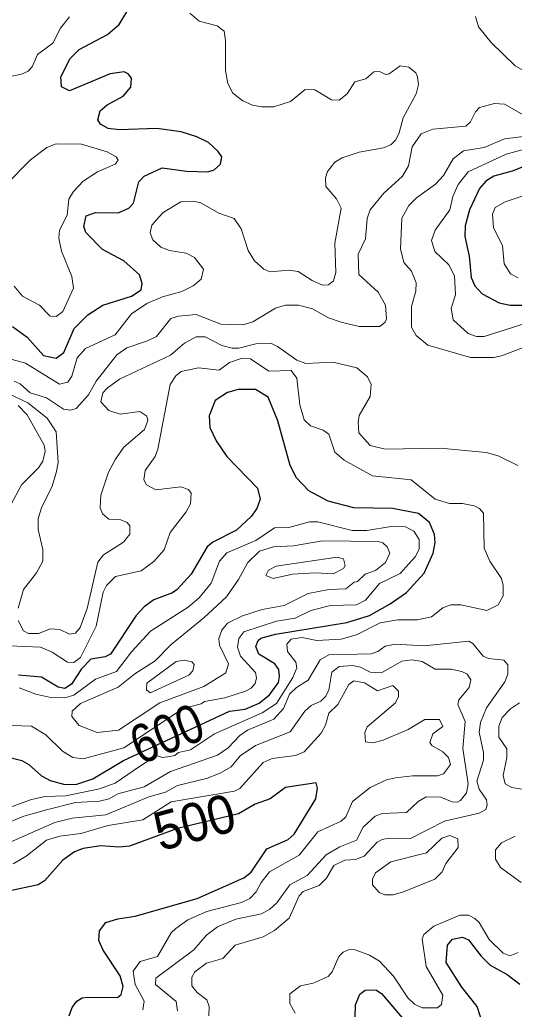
# Model space of a CAD drawing. Extents: x 577 to 602.9, y 7483.8 to 7511.6.
# Drawn here: x 588.93 to 589.958, y 7495.736 to 7497.794 of the extents above; entities that cross this region are included whole.
import ezdxf
from ezdxf.enums import TextEntityAlignment as Align

# ---------------------------------------------------------------- set-up
doc = ezdxf.new("R2010")
doc.units = 0
doc.header["$LTSCALE"] = 0.032
doc.layers.add('1', color=7, linetype='Continuous', lineweight=25)
doc.layers.add('2', color=7, linetype='Continuous', lineweight=13)
doc.layers.add('61', color=7, linetype='Continuous')

msp = doc.modelspace()

# ---------------------------------------------------------------- linework, layer by layer
at = {"layer": '1'}
for points in [[(589.277, 7497.4791), (589.3215, 7497.4775), (589.3342, 7497.4822), (589.3477, 7497.4934), (589.3501, 7497.5093), (589.343, 7497.5204), (589.3223, 7497.5387), (589.2984, 7497.5506), (589.2658, 7497.561), (589.215, 7497.5681), (589.137, 7497.5649), (589.114, 7497.5681), (589.0981, 7497.5769), (589.0925, 7497.5856), (589.0973, 7497.6047), (589.1116, 7497.6174), (589.145, 7497.6349), (589.1609, 7497.654), (589.1625, 7497.6723), (589.1553, 7497.6818), (589.1474, 7497.6858), (589.1179, 7497.6818), (589.0337, 7497.6461), (589.017, 7497.6548), (589.0154, 7497.6755), (589.0352, 7497.7136), (589.0535, 7497.7319), (589.1124, 7497.7637), (589.137, 7497.7844), (589.1688, 7497.8377)], [(590.061, 7497.5212), (589.9537, 7497.4791), (589.9155, 7497.4687), (589.8988, 7497.4584), (589.8861, 7497.4433), (589.8654, 7497.3988), (589.8559, 7497.3654), (589.8551, 7497.3431), (589.8646, 7497.3025), (589.8686, 7497.258), (589.8765, 7497.2405), (589.8916, 7497.2238), (589.9266, 7497.2055), (589.9497, 7497.2008), (589.991, 7497.2008)], [(588.9152, 7497.1562), (588.9454, 7497.134), (588.9796, 7497.0958), (589.0058, 7497.0902), (589.0217, 7497.1022), (589.0432, 7497.1522), (589.0718, 7497.1801), (589.1028, 7497.2008), (589.1625, 7497.219), (589.1824, 7497.2326), (589.1847, 7497.2453), (589.1792, 7497.2636), (589.1466, 7497.293), (589.102, 7497.3161), (589.0678, 7497.3518), (589.0631, 7497.3638), (589.0686, 7497.386), (589.0877, 7497.3932), (589.1346, 7497.3924), (589.1569, 7497.4019), (589.1664, 7497.4123), (589.1776, 7497.4568), (589.1887, 7497.4687), (589.2261, 7497.4862), (589.277, 7497.4791)], [(588.8937, 7496.264), (588.9343, 7496.2537), (588.9494, 7496.245), (588.9756, 7496.2219), (588.9931, 7496.2124), (589.0241, 7496.2036), (589.0488, 7496.2044), (589.0821, 7496.2153), (589.1456, 7496.2538), (589.366, 7496.3563), (589.3986, 7496.3603), (589.4281, 7496.373), (589.4495, 7496.3905), (589.4678, 7496.4159), (589.4702, 7496.4286), (589.4686, 7496.443), (589.4607, 7496.4549), (589.4273, 7496.4748), (589.4209, 7496.4907), (589.4257, 7496.5034), (589.4312, 7496.5082), (589.4619, 7496.5166), (589.6102, 7496.5408), (589.6571, 7496.5551), (589.7, 7496.5797), (589.7342, 7496.6028), (589.7708, 7496.6433), (589.7899, 7496.6847), (589.7938, 7496.7069), (589.7923, 7496.7236), (589.7819, 7496.7483), (589.7589, 7496.7674), (589.7048, 7496.7777), (589.6245, 7496.7793), (589.5712, 7496.7928), (589.5314, 7496.8143), (589.5052, 7496.8413), (589.4925, 7496.8668), (589.467, 7496.9598), (589.4464, 7497.0091), (589.4201, 7497.025), (589.3843, 7497.025), (589.3621, 7497.0187), (589.3366, 7497.002), (589.3239, 7496.9702), (589.3255, 7496.9463), (589.3382, 7496.9185), (589.3605, 7496.8859), (589.4241, 7496.8199), (589.4297, 7496.7968), (589.4233, 7496.7777), (589.4114, 7496.761), (589.3811, 7496.7324), (589.3318, 7496.7077), (589.3199, 7496.6982), (589.2865, 7496.6409), (589.2571, 7496.6091), (589.2476, 7496.602), (589.2086, 7496.5877), (589.1887, 7496.5734), (589.172, 7496.5551), (589.1187, 7496.4748), (589.1076, 7496.4692), (589.0782, 7496.4644), (589.0583, 7496.4445), (589.0376, 7496.4127), (589.0241, 7496.4032), (589.0098, 7496.4064), (588.9756, 7496.427), (588.9279, 7496.431)], [(589.0329, 7495.7225), (589.0392, 7495.74), (589.0488, 7495.7535), (589.0599, 7495.7599), (589.0718, 7495.7615), (589.1331, 7495.7607), (589.141, 7495.7671), (589.145, 7495.7838), (589.1386, 7495.806), (589.1036, 7495.8593), (589.0949, 7495.8792), (589.0957, 7495.8991), (589.1092, 7495.9165), (589.1338, 7495.9245), (589.1704, 7495.9301), (589.2992, 7495.9666), (589.3963, 7496.0096), (589.4114, 7496.0215), (589.444, 7496.07), (589.4885, 7496.0891), (589.5004, 7496.1002), (589.5457, 7496.1742), (589.5489, 7496.1964), (589.5464, 7496.2074), (589.4829, 7496.1972), (589.4511, 7496.1742), (589.4193, 7496.163), (589.3851, 7496.1424), (589.2582, 7496.112), (589.1585, 7496.0756), (589.1362, 7496.0732), (589.0989, 7496.0764), (589.0623, 7496.0708), (589.044, 7496.0637), (589.0201, 7496.0462), (588.982, 7496.0032), (588.9685, 7495.9953), (588.8547, 7495.9706)], [(589.8956, 7495.6971), (589.8813, 7495.7424), (589.8495, 7495.7822), (589.8169, 7495.8338), (589.8193, 7495.8696), (589.8296, 7495.8824), (589.8503, 7495.8863), (589.863, 7495.8808), (589.8893, 7495.8466), (589.9083, 7495.8283), (589.9433, 7495.8084), (589.9696, 7495.7885)], [(589.6277, 7495.7201), (589.6284, 7495.7456), (589.6372, 7495.7678), (589.6483, 7495.7758), (589.6706, 7495.7766), (589.6825, 7495.7694), (589.7334, 7495.709)]]:
    msp.add_lwpolyline(points, dxfattribs=at)
at = {"layer": '2'}
for points in [[(588.9335, 7497.681), (588.9478, 7497.6874), (588.9557, 7497.6961), (588.9669, 7497.7216), (588.9987, 7497.7454), (589.0146, 7497.7765), (589.0337, 7497.8003)], [(589.2841, 7497.8075), (589.3032, 7497.7908), (589.3406, 7497.7812), (589.3549, 7497.7701), (589.3581, 7497.751), (589.3581, 7497.6882), (589.3629, 7497.6612), (589.3732, 7497.6413), (589.3939, 7497.6254), (589.4137, 7497.6166), (589.4328, 7497.6127), (589.4583, 7497.6127), (589.4933, 7497.6238), (589.5235, 7497.6492), (589.5434, 7497.6484), (589.5783, 7497.6278), (589.5943, 7497.627), (589.611, 7497.6397), (589.6269, 7497.6651), (589.6499, 7497.6715), (589.6666, 7497.6858), (589.6777, 7497.6866), (589.6913, 7497.6802), (589.6984, 7497.6818), (589.7207, 7497.6985), (589.739, 7497.6954), (589.7533, 7497.6834), (589.7573, 7497.6755), (589.7589, 7497.6596), (589.7541, 7497.6397), (589.727, 7497.5904), (589.7191, 7497.5586), (589.7119, 7497.5443), (589.7024, 7497.5347), (589.6865, 7497.5276), (589.6356, 7497.5188), (589.6006, 7497.5069), (589.5855, 7497.4981), (589.5696, 7497.4783), (589.5656, 7497.4655), (589.5664, 7497.4473), (589.5887, 7497.4218), (589.5982, 7497.4019), (589.5855, 7497.3296), (589.5871, 7497.2683), (589.5823, 7497.2508), (589.572, 7497.2429), (589.5593, 7497.2421), (589.5378, 7497.2516)], [(590.5493, 7497.8114), (590.4809, 7497.7908), (590.4276, 7497.7494), (590.368, 7497.7319), (590.3505, 7497.716), (590.3354, 7497.6906), (590.3258, 7497.6842), (590.3123, 7497.6842), (590.2908, 7497.7033), (590.2805, 7497.7049), (590.2598, 7497.6985), (590.2296, 7497.6779), (590.2034, 7497.6707), (590.158, 7497.6755), (590.1008, 7497.6612), (590.0515, 7497.6612), (589.9958, 7497.6779), (589.96, 7497.6985), (589.9099, 7497.747), (589.8837, 7497.7796), (589.8773, 7497.8011)], [(588.8738, 7497.6683), (588.9335, 7497.681)], [(589.9879, 7497.5904), (589.9378, 7497.6182), (589.9171, 7497.6198), (589.8861, 7497.6119), (589.8773, 7497.6023), (589.867, 7497.5816), (589.8575, 7497.5729), (589.7891, 7497.5665), (589.7644, 7497.557), (589.7461, 7497.53), (589.7382, 7497.4902), (589.7255, 7497.4687), (589.6873, 7497.4337), (589.6587, 7497.3988), (589.6523, 7497.3805), (589.6491, 7497.3383), (589.634, 7497.3065), (589.6348, 7497.2644), (589.6754, 7497.2278), (589.6905, 7497.2008), (589.6929, 7497.1721), (589.6897, 7497.165), (589.6785, 7497.1562), (589.6356, 7497.1562), (589.5982, 7497.165), (589.572, 7497.1745)], [(589.9751, 7497.1117), (589.9314, 7497.095), (589.9155, 7497.0918), (589.867, 7497.0918), (589.7787, 7497.1173), (589.7541, 7497.1371), (589.7445, 7497.1546), (589.7445, 7497.1976), (589.7533, 7497.2294), (589.7541, 7497.2469), (589.7445, 7497.2715), (589.7286, 7497.289), (589.7215, 7497.3176), (589.7247, 7497.3813), (589.739, 7497.4075), (589.7549, 7497.4234), (589.7946, 7497.452), (589.8113, 7497.4703), (589.8312, 7497.5045), (589.8527, 7497.5212), (589.8956, 7497.5284), (589.9378, 7497.5467), (590.0459, 7497.5594)], [(590.092, 7497.5554), (589.941, 7497.5148), (589.8622, 7497.4775), (589.8416, 7497.4512), (589.8304, 7497.4266), (589.8241, 7497.3988), (589.7938, 7497.3566), (589.7859, 7497.3351), (589.793, 7497.3121), (589.8225, 7497.2842), (589.8336, 7497.2612), (589.836, 7497.2222), (589.8272, 7497.1944), (589.8312, 7497.1697), (589.8622, 7497.1419), (589.8797, 7497.1355), (589.8956, 7497.1355), (590.0173, 7497.1745)], [(588.9184, 7497.2397), (588.9358, 7497.219), (588.9716, 7497.2008), (588.9931, 7497.1777), (589.0058, 7497.1769), (589.0201, 7497.1872), (589.0416, 7497.2357), (589.0384, 7497.2604), (589.017, 7497.3129), (589.0114, 7497.3399), (589.013, 7497.3566), (589.0289, 7497.3876), (589.0321, 7497.421), (589.0416, 7497.4369), (589.0623, 7497.4584), (589.0917, 7497.4775), (589.1283, 7497.4934), (589.1346, 7497.5021), (589.1307, 7497.5093), (589.1116, 7497.5196), (589.0583, 7497.5355), (589.0058, 7497.5363), (588.9867, 7497.5284), (588.9525, 7497.5029), (588.9001, 7497.4496)], [(589.9664, 7497.2572), (589.9505, 7497.266), (589.937, 7497.2866), (589.9338, 7497.3248), (589.9147, 7497.3614), (589.9131, 7497.39), (589.9187, 7497.4035), (589.9394, 7497.4155), (590.0308, 7497.4457)], [(589.5378, 7497.2516), (589.5092, 7497.2707), (589.4893, 7497.2731), (589.4511, 7497.2699), (589.4376, 7497.2755), (589.4185, 7497.293), (589.405, 7497.3145), (589.3907, 7497.359), (589.3756, 7497.3805), (589.3438, 7497.3916), (589.3064, 7497.4131), (589.2913, 7497.417), (589.2651, 7497.4155), (589.2285, 7497.3932), (589.2197, 7497.3844), (589.2046, 7497.3669), (589.2014, 7497.351), (589.207, 7497.3367), (589.2237, 7497.3208), (589.2412, 7497.3145), (589.2762, 7497.3089), (589.2937, 7497.2994), (589.312, 7497.2755), (589.3072, 7497.2548), (589.2905, 7497.2405), (589.2674, 7497.2286), (589.2269, 7497.2175), (589.1943, 7497.2039), (589.1625, 7497.1825), (589.1283, 7497.1387), (589.0671, 7497.1101), (589.0496, 7497.091), (589.0384, 7497.0529), (589.0305, 7497.0401), (589.013, 7497.0362), (588.9422, 7497.0799), (588.9017, 7497.091)], [(589.572, 7497.1745), (589.5386, 7497.1928), (589.51, 7497.2008), (589.4829, 7497.2008), (589.4615, 7497.1944), (589.4145, 7497.1658), (589.3939, 7497.1594), (589.3485, 7497.161), (589.2969, 7497.1809), (589.2603, 7497.1777), (589.2444, 7497.1729), (589.2142, 7497.1355), (589.1959, 7497.126), (589.1529, 7497.1117), (589.1323, 7497.0974), (589.0893, 7497.0425), (589.0734, 7497.0139), (589.0472, 7496.9853), (589.036, 7496.9821), (589.0209, 7496.9845), (588.9859, 7497.0075), (588.9518, 7497.0179), (588.9311, 7497.0369), (588.9184, 7497.0425)], [(588.9271, 7496.5447), (588.9382, 7496.5233), (588.9486, 7496.5177), (588.9692, 7496.5177), (588.9939, 7496.5272), (589.0138, 7496.5264), (589.0337, 7496.5161), (589.0464, 7496.5185), (589.0559, 7496.5304), (589.0702, 7496.5694), (589.0925, 7496.6664), (589.1044, 7496.6815), (589.1458, 7496.7077), (589.1593, 7496.7244), (589.1593, 7496.7419), (589.1537, 7496.7483), (589.1402, 7496.7539), (589.1156, 7496.7555), (589.102, 7496.7666), (589.0973, 7496.7793), (589.0989, 7496.8056), (589.1148, 7496.8533), (589.1291, 7496.8803), (589.1466, 7496.9049), (589.1895, 7496.9423), (589.1967, 7496.9606), (589.1943, 7496.9694), (589.18, 7496.9797), (589.1386, 7496.9741), (589.1156, 7496.9813), (589.0989, 7496.9996), (589.1028, 7497.0179), (589.1116, 7497.0282), (589.1378, 7497.0465), (589.2436, 7497.0966), (589.273, 7497.1212), (589.2969, 7497.1348), (589.3159, 7497.1348), (589.3501, 7497.1165), (589.3716, 7497.1109), (589.3859, 7497.1109), (589.4209, 7497.1204), (589.4519, 7497.1212), (589.4662, 7497.1149), (589.506, 7497.0862), (589.5251, 7497.0791), (589.5815, 7497.0823), (589.6308, 7497.0703), (589.6531, 7497.0513), (589.661, 7497.0354), (589.6587, 7497.0107), (589.6356, 7496.9709), (589.634, 7496.9574), (589.6348, 7496.9352), (589.6587, 7496.9089), (589.6897, 7496.901), (589.805, 7496.9034), (589.8996, 7496.8938), (589.925, 7496.8875), (589.9656, 7496.8668)], [(588.908, 7496.4923), (588.9732, 7496.4891), (588.9979, 7496.4787), (589.0297, 7496.4581), (589.0424, 7496.4573), (589.0567, 7496.4676), (589.0893, 7496.5328), (589.1036, 7496.6036), (589.1108, 7496.6179), (589.1291, 7496.6362), (589.1824, 7496.6481), (589.2086, 7496.6672), (589.2301, 7496.6918), (589.2428, 7496.7276), (589.2762, 7496.7706), (589.2849, 7496.7873), (589.2865, 7496.8095), (589.281, 7496.8175), (589.2651, 7496.823), (589.2134, 7496.8167), (589.1935, 7496.827), (589.1879, 7496.8374), (589.1911, 7496.8564), (589.2118, 7496.8859), (589.2173, 7496.901), (589.2428, 7497.0354), (589.2547, 7497.0536), (589.2658, 7497.0624), (589.3016, 7497.0703), (589.3446, 7497.0656), (589.366, 7497.0815), (589.3923, 7497.0902), (589.4098, 7497.0886), (589.4479, 7497.0632), (589.4941, 7497.0648), (589.506, 7497.0489), (589.5124, 7496.9932), (589.5211, 7496.9622), (589.5346, 7496.9495), (589.5609, 7496.9407), (589.5728, 7496.932), (589.5855, 7496.8946), (589.6046, 7496.8779), (589.6634, 7496.8453), (589.7437, 7496.8374), (589.7938, 7496.7968), (589.8233, 7496.7881), (589.8503, 7496.7881), (589.875, 7496.7833), (589.8861, 7496.7777), (589.894, 7496.7682), (589.8956, 7496.695), (589.9076, 7496.668), (589.9314, 7496.6322), (589.9354, 7496.6179), (589.9354, 7496.5964), (589.925, 7496.5773), (589.9012, 7496.5654), (589.8471, 7496.5773), (589.8264, 7496.5773), (589.8097, 7496.571), (589.7859, 7496.5527), (589.7565, 7496.5463), (589.7159, 7496.5463), (589.6793, 7496.54), (589.63, 7496.5153), (589.5982, 7496.5058), (589.5481, 7496.5034)], [(588.9064, 7497.0171), (588.947, 7496.9972), (588.9875, 7496.9654), (589.0058, 7496.9368), (589.0098, 7496.8731), (589.0058, 7496.8517), (588.9971, 7496.8223), (588.9764, 7496.7809), (588.9685, 7496.757), (588.9685, 7496.734), (588.978, 7496.6926), (588.978, 7496.668), (588.9653, 7496.6441), (588.9382, 7496.6091), (588.9271, 7496.5702)], [(588.9112, 7496.7841), (588.9335, 7496.827), (588.9692, 7496.862), (588.978, 7496.8763), (588.9828, 7496.8962), (588.9812, 7496.9097), (588.9454, 7496.9725), (588.9271, 7496.9916)], [(588.9287, 7496.4048), (588.9637, 7496.3913), (588.9947, 7496.3849), (589.0241, 7496.3841), (589.0424, 7496.3897), (589.0877, 7496.4231), (589.1315, 7496.439), (589.1625, 7496.4795), (589.2022, 7496.5225), (589.2802, 7496.5726), (589.3032, 7496.5916), (589.3279, 7496.6227), (589.3454, 7496.668), (589.3605, 7496.6855), (589.4209, 7496.7109), (589.4599, 7496.7372), (589.4893, 7496.738), (589.5322, 7496.7499), (589.5497, 7496.7499), (589.6213, 7496.7316), (589.6515, 7496.7316), (589.7024, 7496.7403), (589.7318, 7496.7396), (589.7493, 7496.7308), (589.7604, 7496.7133), (589.7604, 7496.6934), (589.7525, 7496.6775), (589.7207, 7496.6425), (589.6777, 7496.6219), (589.6491, 7496.5869), (589.63, 7496.5773), (589.576, 7496.5757), (589.5354, 7496.5654), (589.5028, 7496.5495), (589.4638, 7496.5431), (589.3963, 7496.5209), (589.3859, 7496.5074), (589.3827, 7496.4891), (589.3891, 7496.4708), (589.4201, 7496.4366), (589.4225, 7496.4255), (589.4193, 7496.4135), (589.4114, 7496.404), (589.3994, 7496.3976), (589.3565, 7496.3841), (589.3144, 7496.3762), (589.3072, 7496.3714), (589.2698, 7496.3618), (589.1466, 7496.2799), (589.0623, 7496.2569), (589.0408, 7496.2601), (589.0193, 7496.2728), (588.9844, 7496.307), (588.9549, 7496.3253), (588.8738, 7496.3277)], [(589.9386, 7496.4175), (589.9449, 7496.4334), (589.9449, 7496.4525), (589.9362, 7496.462), (589.9044, 7496.466), (589.8932, 7496.4708), (589.8718, 7496.497), (589.8638, 7496.5018), (589.7708, 7496.4923), (589.7103, 7496.4954), (589.6897, 7496.4915), (589.6746, 7496.4803), (589.661, 7496.4756), (589.5728, 7496.4732), (589.5545, 7496.4628), (589.5298, 7496.4207), (589.5052, 7496.4056), (589.4909, 7496.3913), (589.4782, 7496.3618), (589.4583, 7496.3396), (589.4034, 7496.3165), (589.3875, 7496.3054), (589.3637, 7496.2799), (589.3414, 7496.2648), (589.2436, 7496.2306), (589.1887, 7496.1988), (589.1338, 7496.1845), (589.1164, 7496.1742), (589.0957, 7496.1694), (589.0464, 7496.1662), (588.9859, 7496.1511), (588.939, 7496.1376), (588.8698, 7496.1098)], [(589.5481, 7496.5034), (589.5164, 7496.5096), (589.4941, 7496.5058), (589.4853, 7496.4954), (589.4869, 7496.4803), (589.5044, 7496.4581), (589.506, 7496.4461), (589.498, 7496.4263), (589.4638, 7496.3722), (589.4344, 7496.3531), (589.335, 7496.3094), (589.2849, 7496.276), (589.2603, 7496.2704), (589.2523, 7496.264), (589.242, 7496.2617), (589.2269, 7496.2601), (589.2142, 7496.264), (589.1809, 7496.2424)], [(588.881, 7496.0716), (589.0034, 7496.1249), (589.0392, 7496.1336), (589.1092, 7496.1408), (589.1983, 7496.1782), (589.2332, 7496.1877), (589.2579, 7496.202), (589.3183, 7496.2163), (589.347, 7496.2275), (589.37, 7496.2402), (589.3883, 7496.2632), (589.4201, 7496.2847), (589.4925, 7496.3133), (589.5227, 7496.3563), (589.5362, 7496.3682), (589.5561, 7496.377), (589.5656, 7496.3865), (589.5728, 7496.4), (589.5791, 7496.4374), (589.5943, 7496.4493), (589.6221, 7496.4509), (589.6388, 7496.4477), (589.6587, 7496.4374), (589.6825, 7496.4358), (589.7247, 7496.4604), (589.7453, 7496.4628), (589.7668, 7496.4596), (589.7938, 7496.4437), (589.8272, 7496.4437), (589.8495, 7496.439), (589.8606, 7496.4334), (589.8678, 7496.4215), (589.8646, 7496.4056), (589.8431, 7496.3801), (589.8408, 7496.3698), (589.8559, 7496.3348), (589.8511, 7496.2783), (589.8622, 7496.2052), (589.859, 7496.1861), (589.8463, 7496.1702), (589.84, 7496.167), (589.8288, 7496.1678), (589.8058, 7496.1774), (589.7748, 7496.1782), (589.7581, 7496.1686), (589.7342, 7496.1456), (589.6833, 7496.1432), (589.669, 7496.1376), (589.6443, 7496.1153), (589.63, 7496.0883), (589.5958, 7496.074), (589.5672, 7496.0573), (589.5275, 7496.0144), (589.4917, 7495.9953), (589.4646, 7495.9579), (589.4503, 7495.9444), (589.4328, 7495.9348)], [(588.9168, 7496.039), (588.9438, 7496.0549), (588.9859, 7496.0883), (589.0138, 7496.0963), (589.0575, 7496.1018), (589.114, 7496.1185), (589.1863, 7496.1304), (589.2452, 7496.1678), (589.3764, 7496.1901), (589.3875, 7496.1957), (589.436, 7496.2497), (589.4551, 7496.2577), (589.5036, 7496.264), (589.5211, 7496.272), (589.5569, 7496.3102), (589.5656, 7496.3269), (589.5728, 7496.3523), (589.5911, 7496.3698), (589.6141, 7496.4119), (589.6245, 7496.4191), (589.6467, 7496.4151), (589.6738, 7496.3984), (589.7056, 7496.4096), (589.7175, 7496.3976), (589.7175, 7496.3865), (589.7111, 7496.3738), (589.6523, 7496.3237), (589.6475, 7496.3117), (589.6491, 7496.2927), (589.6642, 7496.2903), (589.6857, 7496.2958), (589.7374, 7496.3181), (589.7724, 7496.3388), (589.8026, 7496.3388), (589.8097, 7496.3245), (589.7891, 7496.3094), (589.7827, 7496.2911), (589.7867, 7496.2847), (589.8097, 7496.272), (589.8217, 7496.2601), (589.8256, 7496.245), (589.8113, 7496.2259), (589.7986, 7496.2219)], [(589.3231, 7495.7225), (589.3239, 7495.7424), (589.3191, 7495.7559), (589.2992, 7495.771), (589.2881, 7495.7853), (589.2881, 7495.8028), (589.2945, 7495.814), (589.3183, 7495.8323), (589.3525, 7495.8418), (589.378, 7495.8696), (589.436, 7495.8871), (589.4599, 7495.8998), (589.4901, 7495.9261), (589.5108, 7495.9722), (589.5195, 7495.981), (589.5529, 7495.9937), (589.568, 7496.0088), (589.5831, 7496.035), (589.6062, 7496.0462), (589.6284, 7496.0477), (589.6459, 7496.0549), (589.673, 7496.0835), (589.6833, 7496.0891), (589.6984, 7496.0923), (589.7422, 7496.0915), (589.8129, 7496.1273), (589.8853, 7496.144), (589.8988, 7496.1519), (589.902, 7496.1607), (589.9004, 7496.1718), (589.8853, 7496.1941), (589.8805, 7496.2108), (589.894, 7496.2545), (589.894, 7496.2704), (589.8853, 7496.3125), (589.8877, 7496.3324), (589.9004, 7496.3634), (589.9386, 7496.4175)], [(589.9783, 7496.1933), (589.9529, 7496.1972), (589.9394, 7496.2052), (589.9354, 7496.2227), (589.9425, 7496.2601), (589.9425, 7496.2776), (589.9258, 7496.3022), (589.9258, 7496.3253), (589.933, 7496.3428), (589.9505, 7496.361), (589.9688, 7496.3738)], [(589.1809, 7496.2424), (589.1283, 7496.2068), (589.0957, 7496.1949), (589.0257, 7496.1805), (588.9828, 7496.179), (588.9549, 7496.1726), (588.8531, 7496.136)], [(589.7986, 7496.2219), (589.7469, 7496.2219), (589.7111, 7496.2179), (589.6929, 7496.2131), (589.6587, 7496.1972), (589.6221, 7496.1686), (589.6078, 7496.1368), (589.5982, 7496.1273), (589.5497, 7496.105), (589.5108, 7496.0565), (589.4495, 7496.0223), (589.432, 7496), (589.4217, 7495.9802), (589.4082, 7495.9666), (589.3915, 7495.9587), (589.3191, 7495.9396), (589.2794, 7495.9221), (589.2547, 7495.9046), (589.2452, 7495.8951), (589.2165, 7495.8458), (589.1808, 7495.8354), (589.1657, 7495.8156), (589.1704, 7495.7877), (589.1887, 7495.7535), (589.1863, 7495.7352)], [(589.9728, 7496), (589.9298, 7496.031), (589.9195, 7496.0485), (589.9195, 7496.0676), (589.9314, 7496.0827), (589.96, 7496.0963)], [(589.4328, 7495.9348), (589.3796, 7495.9237), (589.3414, 7495.9078), (589.3183, 7495.8903), (589.2921, 7495.8601), (589.2134, 7495.8012), (589.2126, 7495.7877), (589.2555, 7495.7527), (589.2579, 7495.7329)], [(589.7366, 7495.7599), (589.7509, 7495.7472), (589.7668, 7495.7392), (589.7986, 7495.7392), (589.8066, 7495.7464), (589.8097, 7495.7655), (589.7748, 7495.8251), (589.7668, 7495.8831), (589.77, 7495.8919), (589.7907, 7495.9094), (589.8447, 7495.9317), (589.863, 7495.9317), (589.8765, 7495.9253), (589.8853, 7495.9165), (589.906, 7495.8816), (589.9354, 7495.8529), (589.9489, 7495.8474), (589.9664, 7495.8545)], [(589.5028, 7495.7281), (589.4917, 7495.748), (589.4917, 7495.7686), (589.5139, 7495.7853), (589.5402, 7495.7909), (589.5712, 7495.8044), (589.5799, 7495.814), (589.5935, 7495.8458), (589.6022, 7495.8553), (589.6149, 7495.8609), (589.6277, 7495.8601), (589.6571, 7495.849), (589.6777, 7495.8362), (589.7072, 7495.8052), (589.7366, 7495.7599)]]:
    msp.add_lwpolyline(points, dxfattribs=at)
for points in [[(589.3589, 7496.4358), (589.3128, 7496.4072), (589.2213, 7496.3738), (589.1354, 7496.3165), (589.0909, 7496.3117), (589.0535, 7496.3261), (589.0384, 7496.3451), (589.0392, 7496.3563), (589.0567, 7496.3722), (589.1346, 7496.4064), (589.1696, 7496.4342), (589.2118, 7496.4612), (589.2452, 7496.4946), (589.3128, 7496.5503), (589.3597, 7496.594), (589.3851, 7496.6298), (589.4042, 7496.6656), (589.4289, 7496.6887), (589.4575, 7496.6982), (589.4996, 7496.6998), (589.5593, 7496.7101), (589.6762, 7496.7093), (589.6849, 7496.7062), (589.6937, 7496.6982), (589.6992, 7496.6847), (589.6905, 7496.6656), (589.6698, 7496.6489), (589.6483, 7496.6409), (589.6324, 7496.6258), (589.6253, 7496.6243), (589.6078, 7496.6107), (589.5728, 7496.6091), (589.5298, 7496.6012), (589.4797, 7496.5757), (589.4344, 7496.5678), (589.3931, 7496.5543), (589.3621, 7496.5392), (589.3501, 7496.5249), (589.3438, 7496.5074), (589.3454, 7496.4938), (589.3644, 7496.4549)], [(589.4416, 7496.6386), (589.4567, 7496.6322), (589.4972, 7496.6409), (589.5442, 7496.6441), (589.5815, 7496.6417), (589.603, 7496.6529), (589.607, 7496.6592), (589.603, 7496.6728), (589.5903, 7496.6767), (589.463, 7496.6576), (589.4471, 7496.6497)], [(589.2817, 7496.431), (589.2014, 7496.3944), (589.1935, 7496.4008), (589.1943, 7496.4143), (589.2555, 7496.4596), (589.2722, 7496.462), (589.2881, 7496.4589), (589.2929, 7496.4533), (589.2899, 7496.4398)], [(589.7278, 7495.9802), (589.793, 7496.0072), (589.8082, 7496.0223), (589.8161, 7496.0398), (589.8416, 7496.0724), (589.8408, 7496.0907), (589.8241, 7496.0978), (589.8074, 7496.0923), (589.7756, 7496.0613), (589.7016, 7496.043), (589.6698, 7496.0199), (589.6634, 7496.0072), (589.6634, 7495.9953), (589.677, 7495.9794), (589.6889, 7495.9746), (589.7064, 7495.9746)]]:
    msp.add_lwpolyline(points, close=True, dxfattribs=at)

# ---------------------------------------------------------------- texts
at = {"layer": '61'}
for s, rotation, width, p in [('600', 21.967, 0.85, (589.2509, 7496.2724)), ('500', 15.289, 0.95, (589.3041, 7496.0871))]:
    msp.add_text(s, height=0.08, rotation=rotation, dxfattribs=dict(at, width=width)).set_placement(p, align=Align.CENTER)

doc.saveas('drawing.dxf')
